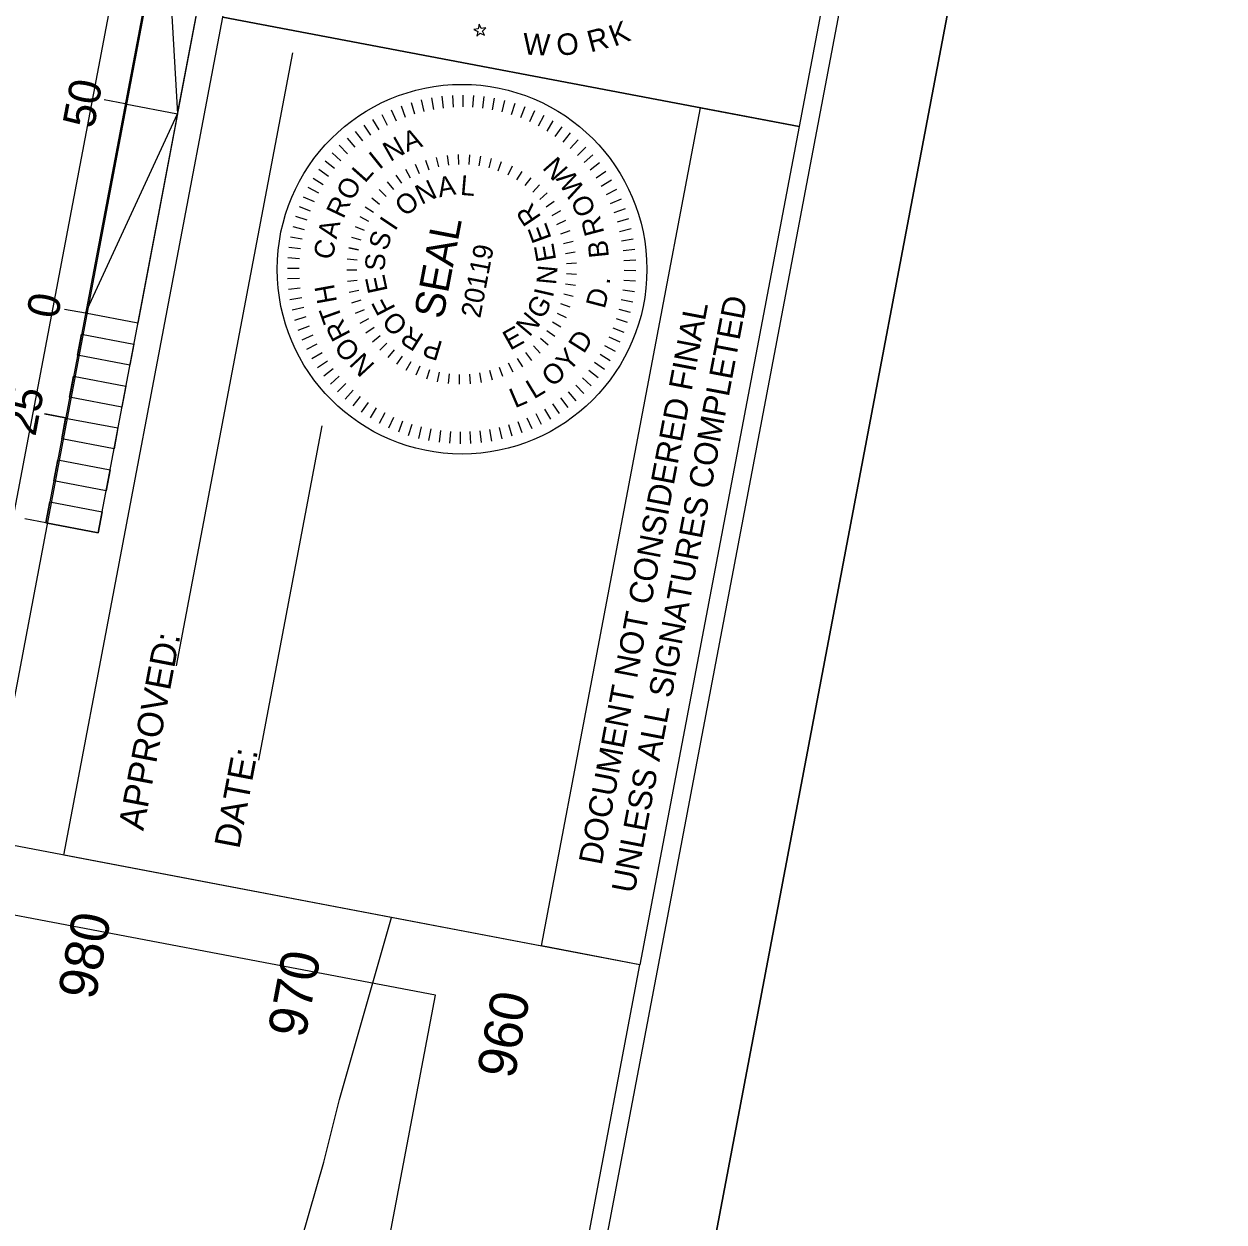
# Model space of a CAD drawing. Extents: x 1615680 to 1619687, y 899305 to 902270.
# Drawn here: x 1616793.9 to 1617075.3, y 900338.4 to 900619.3 of the extents above; entities that cross this region are included whole.
import ezdxf

# ---------------------------------------------------------------- set-up
doc = ezdxf.new("R2010")
doc.units = 0
for name, color, linetype in [('Default', 7, 'Continuous'), ('DEV CRASH CUSHION CELL', 7, 'Continuous'), ('PCB (Plan View)', 7, 'Continuous'), ('Prop Conc 4in Sidewalk', 7, 'Continuous'), ('Prop Conc Drive Radius Type', 7, 'Continuous'), ('Prop Mkg Solid Yel Skip RT Rpm 80ft', 7, 'Continuous'), ('Scratch_Level_3', 7, 'Continuous'), ('Scratch_Level_7', 7, 'Continuous'), ('Scratch_Level_8', 7, 'Continuous'), ('Stage 2', 7, 'Continuous'), ('Stage 2 Pavement Arrows', 7, 'Continuous'), ('Stage 5', 7, 'Continuous'), ('TCP Linework', 7, 'Continuous')]:
    doc.layers.add(name, color=color, linetype=linetype)

msp = doc.modelspace()

# ---------------------------------------------------------------- linework, layer by layer
at = {"layer": 'Default'}
for p, q in [((1616884.69, 900600.85), (1616885.5, 900598.18)), ((1616887.07, 900601.49), (1616887.72, 900598.78)), ((1616889.49, 900601.99), (1616889.97, 900599.25)), ((1616891.93, 900602.35), (1616892.24, 900599.58)), ((1616894.39, 900602.55), (1616894.54, 900599.77)), ((1616896.86, 900602.61), (1616896.84, 900599.82)), ((1616899.33, 900602.51), (1616899.14, 900599.74)), ((1616901.78, 900602.27), (1616901.43, 900599.51)), ((1616904.22, 900601.88), (1616903.7, 900599.15)), ((1616906.64, 900601.35), (1616905.95, 900598.65)), ((1616909.01, 900600.67), (1616908.16, 900598.01)), ((1616877.83, 900598.07), (1616879.11, 900595.59)), ((1616880.06, 900599.13), (1616881.18, 900596.58)), ((1616882.35, 900600.06), (1616883.32, 900597.45)), ((1616911.34, 900599.85), (1616910.33, 900597.25)), ((1616913.61, 900598.89), (1616912.45, 900596.35)), ((1616915.82, 900597.79), (1616914.51, 900595.33)), ((1616873.59, 900595.54), (1616875.15, 900593.24)), ((1616875.67, 900596.87), (1616877.1, 900594.47)), ((1616917.96, 900596.56), (1616916.5, 900594.18)), ((1616920.02, 900595.2), (1616918.43, 900592.92)), ((1616869.68, 900592.52), (1616871.51, 900590.43)), ((1616871.59, 900594.09), (1616873.29, 900591.89)), ((1616922.01, 900593.73), (1616920.27, 900591.54)), ((1616923.89, 900592.13), (1616922.03, 900590.06)), ((1616866.17, 900589.06), (1616868.24, 900587.2)), ((1616867.87, 900590.85), (1616869.82, 900588.86)), ((1616925.68, 900590.42), (1616923.69, 900588.47)), ((1616864.57, 900587.18), (1616866.75, 900585.44)), ((1616885.68, 900586.38), (1616886.63, 900584.26)), ((1616888.11, 900587.31), (1616888.85, 900585.11)), ((1616890.62, 900588.01), (1616891.14, 900585.75)), ((1616893.19, 900588.46), (1616893.48, 900586.16)), ((1616895.78, 900588.66), (1616895.85, 900586.34)), ((1616898.39, 900588.61), (1616898.23, 900586.3)), ((1616900.97, 900588.31), (1616900.59, 900586.02)), ((1616903.52, 900587.76), (1616902.92, 900585.52)), ((1616905.1, 900584.82), (1616905.91, 900587)), ((1616927.35, 900588.62), (1616925.26, 900586.78)), ((1616928.92, 900586.7), (1616926.72, 900585)), ((1616863.1, 900585.2), (1616865.37, 900583.6)), ((1616881.15, 900583.83), (1616882.48, 900581.92)), ((1616883.36, 900585.21), (1616884.49, 900583.19)), ((1616908.39, 900585.94), (1616907.37, 900583.86)), ((1616910.67, 900584.69), (1616909.45, 900582.71)), ((1616930.37, 900584.71), (1616928.07, 900583.14)), ((1616860.51, 900581), (1616862.97, 900579.68)), ((1616861.73, 900583.14), (1616864.11, 900581.67)), ((1616879.09, 900582.24), (1616880.6, 900580.47)), ((1616912.81, 900583.22), (1616911.41, 900581.37)), ((1616914.81, 900581.55), (1616913.24, 900579.84)), ((1616931.69, 900582.62), (1616929.3, 900581.2)), ((1616859.41, 900578.78), (1616861.94, 900577.62)), ((1616875.48, 900578.5), (1616877.29, 900577.06)), ((1616877.19, 900580.46), (1616878.87, 900578.85)), ((1616916.64, 900579.69), (1616914.91, 900578.14)), ((1616932.89, 900580.46), (1616930.42, 900579.19)), ((1616933.96, 900578.24), (1616931.41, 900577.11)), ((1616858.45, 900576.51), (1616861.05, 900575.5)), ((1616873.96, 900576.39), (1616875.91, 900575.13)), ((1616918.28, 900577.67), (1616916.41, 900576.3)), ((1616919.72, 900575.5), (1616917.72, 900574.31)), ((1616934.89, 900575.95), (1616932.27, 900574.98)), ((1616857.63, 900574.18), (1616860.28, 900573.33)), ((1616872.65, 900574.14), (1616874.71, 900573.07)), ((1616920.94, 900573.2), (1616918.84, 900572.21)), ((1616935.68, 900573.61), (1616933.01, 900572.8)), ((1616856.41, 900569.4), (1616859.15, 900568.87)), ((1616856.95, 900571.81), (1616859.65, 900571.12)), ((1616870.71, 900569.31), (1616872.94, 900568.66)), ((1616871.56, 900571.77), (1616873.72, 900570.91)), ((1616921.93, 900570.8), (1616919.74, 900570.01)), ((1616936.32, 900571.22), (1616933.61, 900570.58)), ((1616856.02, 900566.96), (1616858.78, 900566.6)), ((1616870.1, 900566.78), (1616872.38, 900566.35)), ((1616872.38, 900566.35), (1616870.1, 900566.78)), ((1616922.69, 900568.3), (1616920.43, 900567.74)), ((1616936.82, 900568.81), (1616934.08, 900568.32)), ((1616855.78, 900564.5), (1616858.56, 900564.31)), ((1616869.74, 900564.2), (1616872.05, 900563.99)), ((1616923.2, 900565.75), (1616920.9, 900565.4)), ((1616937.18, 900566.37), (1616934.4, 900566.05)), ((1616937.38, 900563.9), (1616934.6, 900563.76)), ((1616855.69, 900562.03), (1616858.47, 900562.01)), ((1616869.62, 900561.61), (1616871.94, 900561.61)), ((1616923.46, 900563.16), (1616921.14, 900563.04)), ((1616937.44, 900561.43), (1616934.65, 900561.46)), ((1616855.74, 900559.57), (1616858.52, 900559.71)), ((1616869.76, 900559.01), (1616872.07, 900559.24)), ((1616923.24, 900557.97), (1616920.94, 900558.29)), ((1616923.48, 900560.56), (1616921.16, 900560.66)), ((1616937.34, 900558.97), (1616934.57, 900559.16)), ((1616855.95, 900557.1), (1616858.72, 900557.42)), ((1616870.15, 900556.43), (1616872.43, 900556.89)), ((1616922.75, 900555.41), (1616920.49, 900555.95)), ((1616937.1, 900556.51), (1616934.34, 900556.87)), ((1616856.3, 900554.66), (1616859.05, 900555.14)), ((1616856.81, 900552.24), (1616859.51, 900552.89)), ((1616870.78, 900553.91), (1616873, 900554.58)), ((1616922.02, 900552.91), (1616919.82, 900553.67)), ((1616936.71, 900554.07), (1616933.98, 900554.59)), ((1616857.45, 900549.86), (1616860.12, 900550.67)), ((1616871.66, 900551.45), (1616873.81, 900552.34)), ((1616872.77, 900549.1), (1616874.82, 900550.19)), ((1616918.93, 900551.45), (1616921.04, 900550.48)), ((1616935.49, 900549.29), (1616932.84, 900550.13)), ((1616936.18, 900551.66), (1616933.48, 900552.35)), ((1616858.24, 900547.52), (1616860.85, 900548.49)), ((1616874.1, 900546.86), (1616876.04, 900548.15)), ((1616918.43, 900546), (1616916.54, 900547.36)), ((1616919.85, 900548.19), (1616917.84, 900549.36)), ((1616934.68, 900546.96), (1616932.08, 900547.96)), ((1616859.17, 900545.23), (1616861.71, 900546.36)), ((1616860.23, 900543.01), (1616862.71, 900544.28)), ((1616875.64, 900544.76), (1616877.44, 900546.23)), ((1616877.37, 900542.82), (1616879.03, 900544.45)), ((1616916.81, 900543.96), (1616915.06, 900545.5)), ((1616933.71, 900544.69), (1616931.18, 900545.84)), ((1616861.43, 900540.84), (1616863.82, 900542.27)), ((1616879.29, 900541.06), (1616880.78, 900542.84)), ((1616881.36, 900539.49), (1616882.67, 900541.41)), ((1616913.02, 900540.4), (1616911.6, 900542.24)), ((1616915, 900542.09), (1616913.41, 900543.79)), ((1616931.39, 900540.33), (1616929.01, 900541.79)), ((1616932.62, 900542.47), (1616930.15, 900543.78)), ((1616862.75, 900538.76), (1616865.06, 900540.33)), ((1616864.2, 900536.76), (1616866.41, 900538.46)), ((1616883.58, 900538.13), (1616884.7, 900540.16)), ((1616885.92, 900536.98), (1616886.84, 900539.12)), ((1616906.23, 900536.59), (1616905.4, 900538.76)), ((1616908.62, 900537.64), (1616907.58, 900539.72)), ((1616910.88, 900538.92), (1616909.65, 900540.88)), ((1616930.03, 900538.27), (1616927.75, 900539.87)), ((1616865.77, 900534.85), (1616867.87, 900536.68)), ((1616888.36, 900536.07), (1616889.06, 900538.28)), ((1616890.87, 900535.4), (1616891.37, 900537.67)), ((1616893.44, 900534.97), (1616893.71, 900537.28)), ((1616896.04, 900534.8), (1616896.08, 900537.12)), ((1616898.64, 900534.87), (1616898.46, 900537.19)), ((1616901.23, 900535.2), (1616900.82, 900537.49)), ((1616903.76, 900535.78), (1616903.14, 900538.01)), ((1616926.96, 900534.4), (1616924.89, 900536.27)), ((1616928.55, 900536.29), (1616926.37, 900538.02)), ((1616867.45, 900533.04), (1616869.43, 900535)), ((1616869.23, 900531.34), (1616871.1, 900533.41)), ((1616923.44, 900530.94), (1616921.61, 900533.04)), ((1616925.25, 900532.62), (1616923.3, 900534.6)), ((1616871.12, 900529.74), (1616872.85, 900531.92)), ((1616873.1, 900528.27), (1616874.69, 900530.55)), ((1616919.53, 900527.93), (1616917.97, 900530.23)), ((1616921.53, 900529.37), (1616919.83, 900531.58)), ((1616875.16, 900526.91), (1616876.62, 900529.28)), ((1616877.3, 900525.68), (1616878.61, 900528.14)), ((1616879.52, 900524.58), (1616880.67, 900527.11)), ((1616915.29, 900525.4), (1616914.02, 900527.88)), ((1616917.45, 900526.6), (1616916.03, 900528.99)), ((1616881.79, 900523.62), (1616882.79, 900526.22)), ((1616884.12, 900522.8), (1616884.96, 900525.45)), ((1616886.49, 900522.12), (1616887.17, 900524.82)), ((1616888.9, 900521.58), (1616889.42, 900524.32)), ((1616906.05, 900521.98), (1616905.41, 900524.69)), ((1616908.44, 900522.62), (1616907.63, 900525.29)), ((1616910.78, 900523.41), (1616909.81, 900526.02)), ((1616913.07, 900524.34), (1616911.94, 900526.88)), ((1616891.34, 900521.19), (1616891.7, 900523.96)), ((1616893.8, 900520.95), (1616893.99, 900523.73)), ((1616896.26, 900520.86), (1616896.28, 900523.64)), ((1616898.73, 900520.91), (1616898.59, 900523.7)), ((1616901.19, 900521.12), (1616900.88, 900523.89)), ((1616903.63, 900521.47), (1616903.15, 900524.22))]:
    msp.add_line(p, q, dxfattribs=at)
at = {"layer": 'DEV CRASH CUSHION CELL'}
msp.add_lwpolyline([(1616837.46, 900256.47), (1616859.02, 900334.16), (1616864.2, 900352.41), (1616867.89, 900367.12), (1616880.11, 900409.76)], dxfattribs=at)
at = {"layer": 'PCB (Plan View)'}
for p, q in [((1616826.98, 900649.69), (1616799.02, 900502.32)), ((1616811.3, 900499.99), (1616839.28, 900647.36)), ((1616817.66, 900600.57), (1616812.76, 900601.5)), ((1616817.66, 900600.57), (1616829.94, 900598.24)), ((1616808.35, 900551.44), (1616803.44, 900552.37)), ((1616805.54, 900536.71), (1616817.82, 900534.38)), ((1616803.69, 900526.88), (1616798.76, 900527.82)), ((1616799.02, 900502.32), (1616794.12, 900503.25)), ((1616799.02, 900502.32), (1616811.3, 900499.99))]:
    msp.add_line(p, q, dxfattribs=at)
for points in [[(1616826.98, 900649.69), (1616829.94, 900598.24), (1616839.28, 900647.36)], [(1616808.35, 900551.44), (1616829.94, 900598.24), (1616820.63, 900549.11)], [(1616806.47, 900541.62), (1616807.41, 900546.53), (1616819.7, 900544.2), (1616818.75, 900539.29)], [(1616804.62, 900531.79), (1616805.54, 900536.71), (1616817.82, 900534.38), (1616816.89, 900529.46)], [(1616802.76, 900521.97), (1616803.69, 900526.88), (1616815.96, 900524.55), (1616815.03, 900519.64)], [(1616800.88, 900512.15), (1616801.82, 900517.06), (1616814.11, 900514.73), (1616813.18, 900509.83)], [(1616799.02, 900502.32), (1616799.95, 900507.23), (1616812.23, 900504.9), (1616811.3, 900499.99)]]:
    msp.add_lwpolyline(points, close=True, dxfattribs=at)
at = {"layer": 'Prop Conc 4in Sidewalk'}
msp.add_lwpolyline([(1616176.29, 901060.7), (1616848.46, 900914.27), (1616896.28, 900812.91), (1616872.94, 900688.21), (1616835.87, 900695.21), (1616753.94, 900262.18), (1616898.09, 900233.43), (1616734.79, 899562.1), (1616202.98, 899609.43), (1616198.71, 899647.14), (1615822.69, 899825.07), (1616054.34, 901080.76)], close=True, dxfattribs=at)
at = {"layer": 'Prop Conc Drive Radius Type'}
for p, q in [((1616938.37, 900398.7), (1616723.15, 900439.56)), ((1616774.52, 899535.75), (1616938.37, 900398.7))]:
    msp.add_line(p, q, dxfattribs=at)
at = {"layer": 'Scratch_Level_3'}
for p, q in [((1616900.47, 900618.15), (1616899.42, 900617.98)), ((1616899.42, 900617.98), (1616900.35, 900617.48)), ((1616900.35, 900617.48), (1616900.14, 900616.42)), ((1616900.14, 900616.42), (1616900.94, 900617.16)), ((1616900.67, 900619.21), (1616900.47, 900618.15)), ((1616901.14, 900618.23), (1616900.67, 900619.21)), ((1616901.14, 900618.23), (1616900.68, 900619.22)), ((1616900.94, 900617.16), (1616901.91, 900616.65)), ((1616902.23, 900618.35), (1616901.14, 900618.23)), ((1616902.23, 900618.35), (1616901.14, 900618.23)), ((1616901.43, 900617.6), (1616902.23, 900618.35)), ((1616901.43, 900617.6), (1616902.23, 900618.35)), ((1616901.91, 900616.65), (1616901.43, 900617.6))]:
    msp.add_line(p, q, dxfattribs=at)
at = {"layer": 'Scratch_Level_7'}
for p, q in [((1616863.68, 900616.49), (1616975.68, 900595.23)), ((1616829.71, 900468.75), (1616857, 900612.52)), ((1616849, 900446.64), (1616863.88, 900525.03))]:
    msp.add_line(p, q, dxfattribs=at)
for points in [[(1616014.55, 901139.21), (1615734.74, 899665.53), (1616766.32, 899469.67), (1617046.12, 900943.35)], [(1616840.59, 900620.87), (1616861.86, 900732.87), (1616996.95, 900707.23), (1616975.68, 900595.22)], [(1616803.28, 900424.35), (1616840.59, 900620.87), (1616975.68, 900595.22), (1616938.37, 900398.7)]]:
    msp.add_lwpolyline(points, close=True, dxfattribs=at)
msp.add_circle((1616896.65, 900561.78), 43.34, dxfattribs=at)
at = {"layer": 'Scratch_Level_8'}
msp.add_lwpolyline([(1616054.34, 901080.76), (1615793.19, 899705.33), (1616726.52, 899528.12), (1616890.46, 900391.55), (1616774.26, 900413.61), (1616871.48, 900925.61)], close=True, dxfattribs=at)
at = {"layer": 'Stage 2'}
for p, q in [((1616817.65, 900600.58), (1616812.75, 900601.51)), ((1616803.68, 900526.9), (1616798.77, 900527.83)), ((1616799.01, 900502.34), (1616794.11, 900503.27))]:
    msp.add_line(p, q, dxfattribs=at)
at = {"layer": 'Stage 2 Pavement Arrows'}
for p, q in [((1616915.28, 900403.08), (1616952.59, 900599.61)), ((1616952.6, 900599.61), (1616975.69, 900595.22)), ((1616975.68, 900595.22), (1616938.37, 900398.7)), ((1616938.37, 900398.7), (1616915.28, 900403.08))]:
    msp.add_line(p, q, dxfattribs=at)
at = {"layer": 'Stage 5'}
for points in [[(1616760.47, 899304.87), (1615679.78, 899510.06), (1615994.65, 901168.43), (1617075.34, 900963.24)], [(1616760.47, 899304.87), (1617075.34, 900963.24), (1615994.65, 901168.43), (1615679.78, 899510.06)]]:
    msp.add_lwpolyline(points, close=True, dxfattribs=at)

# ---------------------------------------------------------------- texts
at = {"layer": 'Default'}
for s, height, rotation, p in [('N', 4.64, 29.481, (1616879.8, 900586.88)), ('A', 4.64, 19.7134, (1616883.74, 900589.24)), ('I', 4.64, 38.7754, (1616877.22, 900585)), ('N', 4.64, 131.4034, (1616921.77, 900585.19)), ('L', 4.64, 48.3509, (1616873.87, 900581.83)), ('A', 4.64, 10.3632, (1616891.32, 900578.61)), ('L', 4.64, 355.067, (1616896.11, 900579.23)), ('W', 4.64, 122.5208, (1616925.62, 900580.49)), ('O', 4.64, 61.4872, (1616870.95, 900577.58)), ('N', 4.64, 25.6595, (1616887.11, 900576.83)), ('R', 4.64, 64.544, (1616868.8, 900573.42)), ('O', 4.64, 40.9557, (1616883.39, 900573.9)), ('O', 4.64, 113.6381, (1616928.19, 900575.35)), ('R', 4.64, 123.7612, (1616915.36, 900573.97)), ('A', 4.64, 76.5533, (1616867.21, 900568.72)), ('I', 4.64, 56.252, (1616880.91, 900570.56)), ('SEAL', 6.965, 79.1963, (1616892.17, 900549.87)), ('E', 4.64, 109.9902, (1616917.71, 900569.02)), ('R', 4.64, 104.8155, (1616930.05, 900570.31)), ('S', 4.64, 71.5482, (1616879, 900565.9)), ('C', 4.64, 76.5533, (1616866.16, 900563.75)), ('20119', 4.64, 79.1963, (1616900.91, 900550.14)), ('E', 4.64, 100.0043, (1616918.76, 900563.97)), ('B', 4.64, 95.813, (1616931.11, 900564.65)), ('S', 4.64, 86.8445, (1616878.51, 900561.28)), ('N', 4.64, 84.6122, (1616918.68, 900558.01)), ('H', 4.64, 100.264, (1616867.36, 900554.13)), ('E', 4.64, 102.1407, (1616879.26, 900556.7)), ('.', 4.64, 83.0287, (1616931.23, 900558.08)), ('G', 4.64, 58.8877, (1616915.44, 900549.79)), ('I', 4.64, 76.9825, (1616917.93, 900554.94)), ('D', 4.64, 75.2863, (1616930.09, 900552.34)), ('F', 4.64, 117.437, (1616881.15, 900552.56)), ('T', 4.64, 109.6959, (1616868.65, 900550.08)), ('R', 4.64, 117.8569, (1616870.61, 900546.53)), ('O', 4.64, 132.7332, (1616884.24, 900548.83)), ('N', 4.64, 50.1215, (1616912.45, 900545.74)), ('R', 4.64, 148.0295, (1616887.99, 900546.25)), ('E', 4.64, 29.2664, (1616907.92, 900542.64)), ('D', 4.64, 57.491, (1616925.2, 900541.79)), ('O', 4.64, 130.9136, (1616873.05, 900542.64)), ('P', 4.64, 163.3257, (1616892.38, 900544.69)), ('N', 4.64, 132.8731, (1616876.4, 900539.29)), ('Y', 4.64, 48.5185, (1616921.72, 900537.53)), ('O', 4.64, 39.8459, (1616917.75, 900533.99)), ('L', 4.64, 31.2032, (1616913.5, 900531.22)), ('L', 4.64, 23.1314, (1616909.05, 900529.14))]:
    msp.add_text(s, height=height, rotation=rotation, dxfattribs=at).set_placement(p)
at = {"layer": 'PCB (Plan View)'}
for s, p in [('50', (1616810.27, 900594.53)), ('0', (1616801.8, 900549.89)), ('25', (1616796.58, 900522.4))]:
    msp.add_text(s, height=7.5, rotation=79.2541, dxfattribs=at).set_placement(p)
at = {"layer": 'Prop Mkg Solid Yel Skip RT Rpm 80ft'}
for s, rotation, p in [('K', 21.0412, (1616932.34, 900613.91)), ('W', 357.3994, (1616910.86, 900612.13)), ('O', 6.3641, (1616919.07, 900611.76)), ('R', 14.8034, (1616926.77, 900612.58))]:
    msp.add_text(s, height=5.04, rotation=rotation, dxfattribs=at).set_placement(p)
at = {"layer": 'Scratch_Level_7'}
for s, p in [('APPROVED:  ', (1616821.9, 900429.94)), ('DATE:  ', (1616844.4, 900425.67))]:
    msp.add_text(s, height=6, rotation=79.2494, dxfattribs=at).set_placement(p)
at = {"layer": 'Stage 2 Pavement Arrows'}
for s, p in [('UNLESS ALL SIGNATURES COMPLETED', (1616937.07, 900415.23)), ('DOCUMENT NOT CONSIDERED FINAL', (1616929.37, 900421.85))]:
    msp.add_text(s, height=5.5, rotation=79.2494, dxfattribs=at).set_placement(p)
at = {"layer": 'TCP Linework'}
for s, p in [('980', (1616810.63, 900390.2)), ('970', (1616859.82, 900381.22)), ('960', (1616908.9, 900371.68))]:
    msp.add_text(s, height=9, rotation=79.2494, dxfattribs=at).set_placement(p)

doc.saveas('drawing.dxf')
